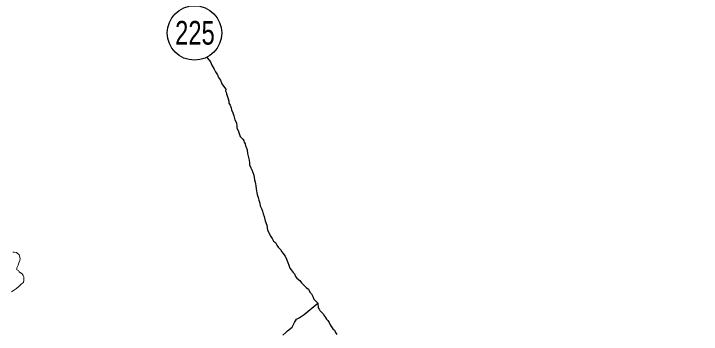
# Model space of a CAD drawing. Extents: x -1643653 to 4543381, y 1624270 to 13878484.
# Drawn here: x 589726 to 591755, y 8907871 to 8908816 of the extents above; entities that cross this region are included whole.
import ezdxf
from ezdxf.enums import TextEntityAlignment as Align

# ---------------------------------------------------------------- set-up
doc = ezdxf.new("R2010")
doc.units = 0
doc.header["$LTSCALE"] = 200
doc.layers.add('1', color=7, linetype='Continuous', lineweight=13)
doc.layers.add('6', color=7, linetype='Continuous', lineweight=13)

msp = doc.modelspace()

# ---------------------------------------------------------------- linework, layer by layer
at = {"layer": '1', "lineweight": 25}
msp.add_spline([(814781, 9009175.5), (814787.2, 9009173.4), (814796.9, 9009173.4), (814799.4, 9009172.4), (814805.1, 9009174.5), (814805.6, 9009176.5), (814811.7, 9009179.5), (814811.7, 9009179.5), (814801.5, 9009181), (814790.7, 9009181.5), (814784.1, 9009183.1), (814777.4, 9009185.1), (814778.4, 9009175.5)], degree=3, dxfattribs=at)
at = {"layer": '6', "lineweight": 25}
for points in [[(590296.3, 8908687.9), (590297.6, 8908684.8), (590306, 8908674.3), (590309.9, 8908664.2), (590316.8, 8908653.2), (590320.8, 8908644.6), (590326.7, 8908636.1), (590329.6, 8908628), (590336.1, 8908620), (590340, 8908609.4), (590347.9, 8908598.4), (590351.4, 8908593.3), (590350.9, 8908589.3), (590352.3, 8908585.3), (590353.3, 8908579.8), (590356.7, 8908570.8), (590358.7, 8908564.8), (590360.6, 8908558.7), (590360.6, 8908552.7), (590364.5, 8908546.2), (590367.5, 8908538.7), (590368.4, 8908532.7), (590371.9, 8908524.1), (590375.3, 8908515.6), (590378.7, 8908503.5), (590382.7, 8908494.5), (590384.6, 8908484.5), (590384.5, 8908479), (590388, 8908471.9), (590393.8, 8908453.9)], [(590393.8, 8908453.9), (590402.3, 8908446.3), (590404.8, 8908441.8), (590406.2, 8908437.8), (590408.7, 8908432.7), (590410.2, 8908426.7), (590411.6, 8908422.7), (590414.6, 8908415.2), (590415.5, 8908403.7), (590418.9, 8908392.6), (590420.3, 8908384.1), (590421.8, 8908376.1), (590421.7, 8908370.6), (590425.7, 8908361.5), (590428.6, 8908355.5), (590434.5, 8908340.4)], [(590434.5, 8908340.4), (590436.4, 8908326.4), (590437.8, 8908319.4), (590439.3, 8908314.9), (590440.3, 8908308.4), (590441.7, 8908299.3), (590443.1, 8908288.3), (590444.6, 8908282.8), (590447.5, 8908274.3), (590448.9, 8908266.2), (590452.4, 8908257.7), (590453.3, 8908249.7), (590457.3, 8908241.7), (590460.2, 8908234.1), (590461.6, 8908226.1), (590464.6, 8908218.6), (590468, 8908205.5), (590472.9, 8908193)], [(590472.9, 8908193), (590474.8, 8908177.9), (590478.7, 8908171.4), (590480.2, 8908165.9), (590484.1, 8908158.9), (590488.6, 8908152.8), (590492, 8908145.3), (590498.5, 8908141.2), (590502.5, 8908133.7), (590505.9, 8908127.2), (590513.4, 8908120.6), (590517.3, 8908114.1), (590520.3, 8908109.6), (590527.2, 8908101), (590530.7, 8908092), (590534.6, 8908082.9), (590538, 8908074.4), (590541, 8908065.3), (590544.4, 8908060.3), (590550.4, 8908053.3), (590554.3, 8908048.7), (590557.8, 8908040.7), (590561.7, 8908036.2), (590569.7, 8908029.6), (590574.7, 8908022.6), (590582.1, 8908015.5), (590588.5, 8908008.5), (590596, 8908003.9), (590600, 8907994.9), (590604.4, 8907989.8), (590608.3, 8907982.3), (590611.8, 8907973.8), (590623.7, 8907962.2)], [(590547.1, 8907892.1), (590554.7, 8907905), (590559.8, 8907915.5), (590568.4, 8907919.5), (590582.9, 8907929.4), (590623.7, 8907962.2)], [(590623.7, 8907962.2), (590624.6, 8907949.1), (590627.1, 8907945.1), (590629.6, 8907941.1), (590633.5, 8907937.1), (590638.5, 8907931), (590642.9, 8907924.5), (590645.4, 8907920.5), (590648.9, 8907914.9), (590652.3, 8907910.9), (590656.3, 8907905.4), (590659.7, 8907898.8), (590663.7, 8907892.3), (590667.2, 8907886.8), (590672.1, 8907882.7), (590675.1, 8907875.7), (590679.5, 8907870.2)], [(590519.9, 8907867.7), (590528.5, 8907876.2), (590534.1, 8907881.1), (590547.1, 8907892.1)]]:
    msp.add_lwpolyline(points, dxfattribs=at)
at = {"layer": '6'}
for points in [[(589741.4, 8908105.2), (589733.5, 8908112.2), (589727, 8908113.3), (589723, 8908113.3)], [(589719.1, 8907995.7), (589727.6, 8908001.6), (589734.2, 8908006.1), (589741.7, 8908012.6), (589748.2, 8908019), (589754.8, 8908023.5), (589755.8, 8908030), (589755.9, 8908036.5), (589755.4, 8908040.5), (589754, 8908044.5), (589750.5, 8908048.6), (589746, 8908051.6), (589741.5, 8908055.1), (589739.6, 8908059.1), (589735.1, 8908060.7), (589735.1, 8908066.7), (589738.7, 8908074.2), (589741.2, 8908081.2), (589743.8, 8908088.7), (589744.3, 8908094.7), (589741.4, 8908105.2)]]:
    msp.add_lwpolyline(points, dxfattribs=at)
at = {"layer": '6', "lineweight": 25}
msp.add_circle((590259.2, 8908759.7), 80.3, dxfattribs=at)

# ---------------------------------------------------------------- texts
at = {"layer": '6', "width": 0.75}
msp.add_text('225', height=70, dxfattribs=at).set_placement((590260.5, 8908725.1), align=Align.CENTER)

doc.saveas('drawing.dxf')
